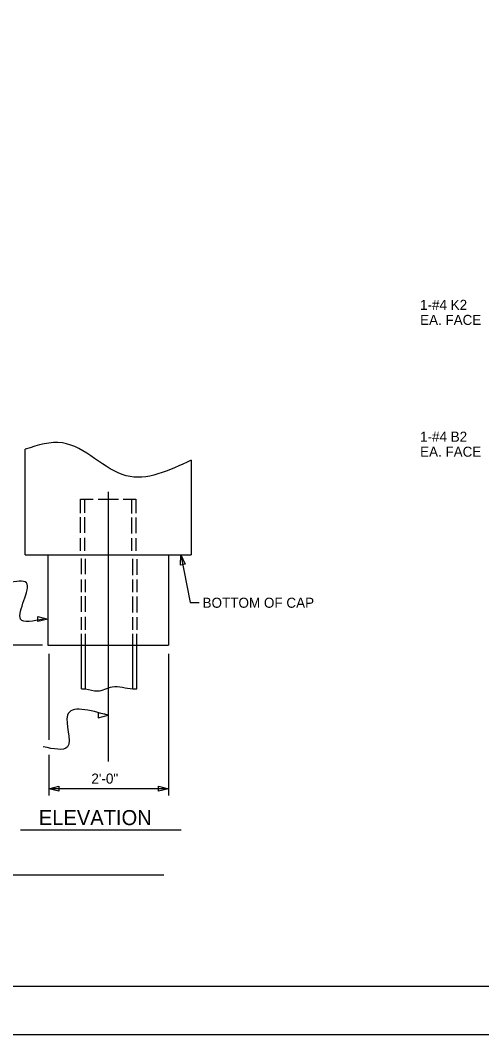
# Model space of a CAD drawing. Extents: x -41 to 251, y -169 to 237.
# Drawn here: x 27.5 to 40.65, y -168.52 to -139.61 of the extents above; entities that cross this region are included whole.
import ezdxf

# ---------------------------------------------------------------- set-up
doc = ezdxf.new("R2010")
doc.units = 0
for name, color, linetype in [('Arrowhead Terminators CELL', 7, 'Continuous'), ('Default', 7, 'Continuous'), ('Dimension Lines', 7, 'Continuous'), ('Dimension Lines CELL', 7, 'Continuous'), ('Mis Center Lines', 7, 'Continuous'), ('Mis Object Lines', 7, 'Continuous'), ('Plan Sheet CELL', 7, 'Continuous'), ('Plot Shape CELL', 7, 'Continuous'), ('Structural Steel Lines CELL', 7, 'Continuous'), ('Subtitle Text', 7, 'Continuous'), ('Text', 7, 'Continuous'), ('Text CELL', 7, 'Continuous')]:
    doc.layers.add(name, color=color, linetype=linetype)

msp = doc.modelspace()

# ---------------------------------------------------------------- linework, layer by layer
at = {"layer": 'Arrowhead Terminators CELL'}
for points in [[(32.079, -154.838), (32.203, -155.105), (32.063, -155.132)], [(28.29, -156.669), (28.004, -156.74), (28.004, -156.598)], [(30.009, -159.413), (29.723, -159.341), (29.723, -159.484)], [(28.315, -161.504), (28.6, -161.433), (28.6, -161.576)], [(31.727, -161.504), (31.442, -161.576), (31.442, -161.433)]]:
    msp.add_lwpolyline(points, close=True, dxfattribs=at)
at = {"layer": 'Default'}
for p, q in [((28.29, -154.838), (28.29, -157.416)), ((31.727, -154.838), (31.727, -157.416)), ((28.29, -157.416), (31.727, -157.416))]:
    msp.add_line(p, q, dxfattribs=at)
at = {"layer": 'Dimension Lines'}
for p, q in [((28.315, -157.661), (28.315, -160.108)), ((31.727, -157.661), (31.727, -161.703)), ((28.315, -160.539), (28.315, -161.703)), ((31.727, -161.504), (28.315, -161.504))]:
    msp.add_line(p, q, dxfattribs=at)
msp.add_lwpolyline([(32.079, -154.838), (32.339, -156.195), (32.599, -156.195)], dxfattribs=at)
at = {"layer": 'Dimension Lines CELL'}
msp.add_line((28.141, -157.416), (24.117, -157.416), dxfattribs=at)
for points in [[(28.164, -156.669), (27.512, -156.669), (27.679, -155.636), (27.16, -155.636)], [(30.009, -159.413), (28.848, -159.413), (28.848, -160.309), (28.154, -160.309)]]:
    msp.add_spline(points, degree=3, dxfattribs=at)
at = {"layer": 'Mis Center Lines'}
msp.add_line((30.009, -153.047), (30.009, -160.733), dxfattribs=at)
at = {"layer": 'Mis Object Lines'}
for p, q in [((27.645, -154.838), (27.645, -151.829)), ((32.373, -152.142), (32.373, -154.838)), ((27.645, -154.838), (32.373, -154.838))]:
    msp.add_line(p, q, dxfattribs=at)
msp.add_spline([(32.373, -152.142), (30.52, -152.589), (28.705, -151.65), (27.645, -151.829)], degree=3, dxfattribs=at)
at = {"layer": 'Plan Sheet CELL'}
msp.add_line((2.412, -167.129), (75.628, -167.129), dxfattribs=at)
at = {"layer": 'Plot Shape CELL'}
msp.add_lwpolyline([(0, -118.18), (75.648, -118.18), (75.648, -168.516), (0, -168.516)], close=True, dxfattribs=at)
at = {"layer": 'Structural Steel Lines CELL'}
for p, q in [((29.338, -153.645), (29.338, -153.257)), ((30.683, -153.663), (30.683, -153.257)), ((29.338, -154.212), (29.338, -153.771)), ((30.683, -154.233), (30.683, -153.774)), ((29.338, -154.724), (29.338, -154.359)), ((30.683, -154.724), (30.683, -154.362)), ((29.363, -155.393), (29.363, -154.952)), ((30.708, -155.415), (30.708, -154.956)), ((29.363, -155.906), (29.363, -155.541)), ((30.708, -155.906), (30.708, -155.544)), ((29.363, -156.463), (29.363, -156.022)), ((30.708, -156.485), (30.708, -156.026)), ((29.363, -156.976), (29.363, -156.61)), ((30.708, -156.976), (30.708, -156.614)), ((29.246, -158.66), (29.246, -157.094)), ((29.363, -158.66), (29.363, -157.094)), ((30.708, -158.66), (30.708, -157.094)), ((30.823, -158.66), (30.823, -157.094))]:
    msp.add_line(p, q, dxfattribs=at)
for points in [[(29.221, -153.648), (29.221, -153.257), (29.581, -153.257)], [(29.721, -153.257), (30.305, -153.257)], [(30.437, -153.257), (30.796, -153.257), (30.796, -153.654)], [(29.221, -154.213), (29.221, -153.766)], [(30.796, -153.778), (30.796, -154.227)], [(29.221, -154.724), (29.221, -154.362)], [(30.796, -154.362), (30.796, -154.724)], [(29.246, -155.395), (29.246, -154.948)], [(30.821, -154.959), (30.821, -155.409)], [(29.246, -155.906), (29.246, -155.543)], [(30.821, -155.543), (30.821, -155.906)], [(29.246, -156.464), (29.246, -156.018)], [(30.821, -156.029), (30.821, -156.479)], [(29.246, -156.976), (29.246, -156.613)], [(30.821, -156.613), (30.821, -156.976)]]:
    msp.add_lwpolyline(points, dxfattribs=at)
msp.add_spline([(29.246, -158.66), (29.363, -158.66), (29.703, -158.718), (30.122, -158.603), (30.708, -158.66), (30.823, -158.66)], degree=3, dxfattribs=at)
at = {"layer": 'Subtitle Text'}
msp.add_line((32.085, -162.684), (27.513, -162.684), dxfattribs=at)
at = {"layer": 'Text CELL'}
msp.add_line((7.321, -163.959), (31.592, -163.959), dxfattribs=at)

# ---------------------------------------------------------------- texts
at = {"layer": 'Subtitle Text'}
msp.add_text('ELEVATION', height=0.4286, rotation=360, dxfattribs=at).set_placement((28.031, -162.542))
at = {"layer": 'Text'}
for s, height, p in [('BOTTOM OF CAP', 0.28702, (32.695, -156.349)), ('2\'-0"', 0.287, (29.528, -161.36))]:
    msp.add_text(s, height=height, rotation=360, dxfattribs=at).set_placement(p)
at = {"layer": 'Text CELL'}
for s, p in [('1-#4 K2', (38.892, -147.859)), ('EA. FACE', (38.892, -148.288)), ('1-#4 B2', (38.892, -151.616)), ('EA. FACE', (38.892, -152.044))]:
    msp.add_text(s, height=0.2859, dxfattribs=at).set_placement(p)

doc.saveas('drawing.dxf')
